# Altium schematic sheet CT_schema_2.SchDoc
size 276 x 169 mm
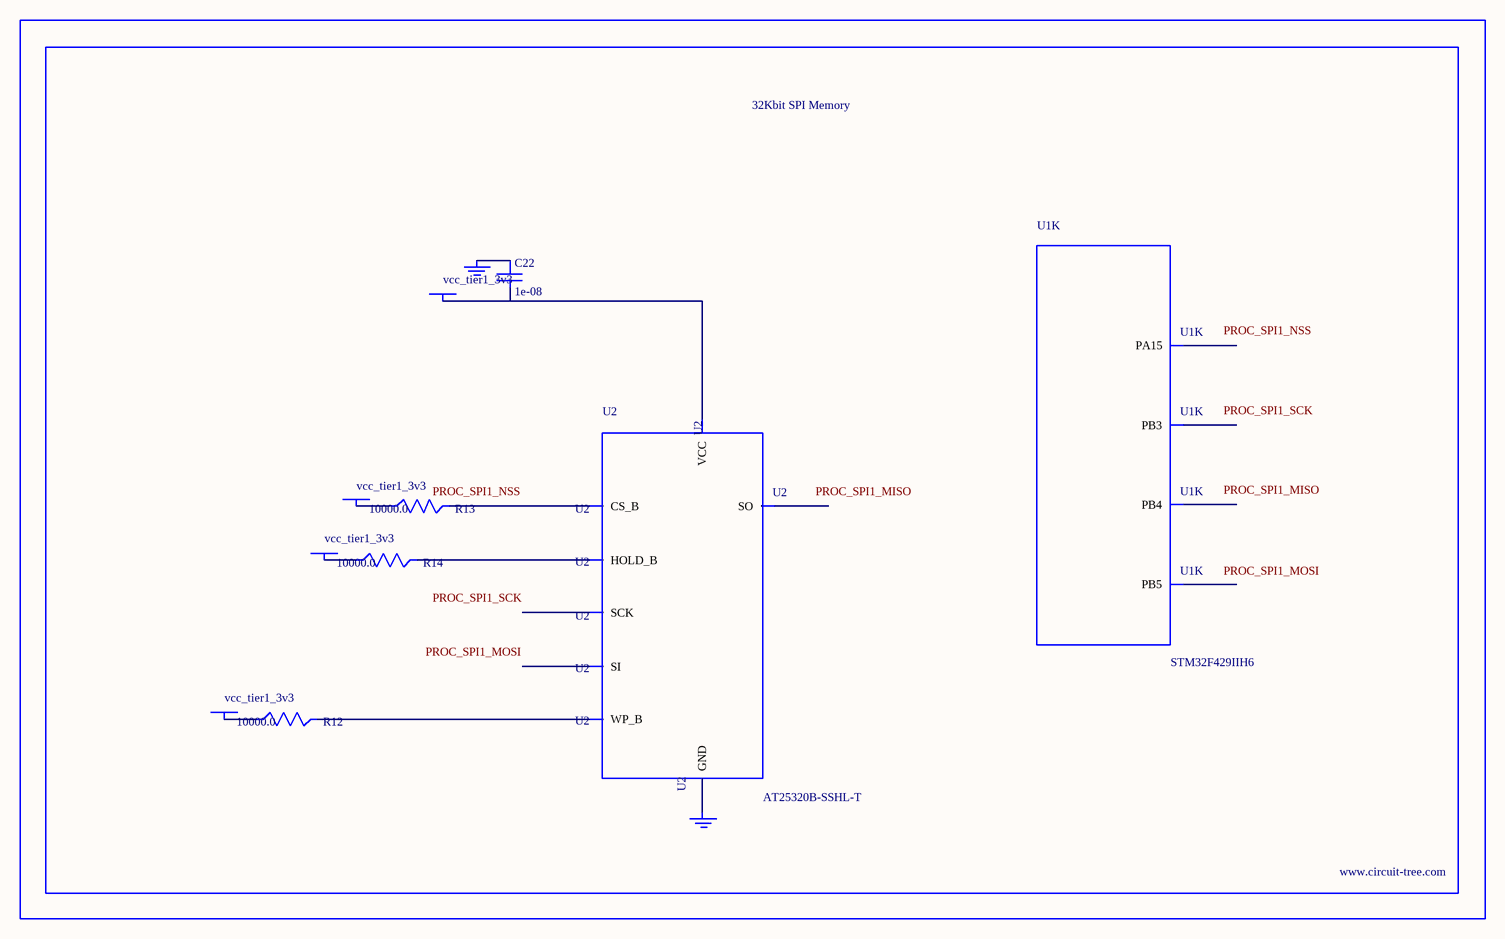
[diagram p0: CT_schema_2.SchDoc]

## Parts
BORDER1  (no value)
C22  1e-08  [C0402]
GND_INSTANCE_1_0  (no value)
GND_INSTANCE_1_1  (no value)
POWER_INSTANCE_1_0  vcc_tier1_3v3
POWER_INSTANCE_1_1  vcc_tier1_3v3
POWER_INSTANCE_1_2  vcc_tier1_3v3
POWER_INSTANCE_1_3  vcc_tier1_3v3
R12  10000.0  [R0603]
R13  10000.0  [R0603]
R14  10000.0  [R0603]
U1  STM32F429IIH6  [UFBGA176_25]  (part K of 16)
U2  AT25320B-SSHL-T  [SOIC-8]

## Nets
NetC22_1: C22.1 GND_INSTANCE_1_0.0(GND)
NetC22_2: C22.2 POWER_INSTANCE_1_3.0(PWR) U2.8(VCC)
NetGND_INSTANCE_1_1_0: GND_INSTANCE_1_1.0(GND) U2.4(GND)
NetPOWER_INSTANCE_1_0_0: POWER_INSTANCE_1_0.0(PWR) R13.1
NetPOWER_INSTANCE_1_1_0: POWER_INSTANCE_1_1.0(PWR) R12.1
NetPOWER_INSTANCE_1_2_0: POWER_INSTANCE_1_2.0(PWR) R14.1
NetR12_2: R12.2 U2.3(WP_B)
NetR13_2: R13.2 U2.1(CS_B)
NetR14_2: R14.2 U2.7(HOLD_B)

Not connected (* = marked no-connect by the designer): U1 A6(PB5) A9(PB4) A10(PB3) A13(PA15); U2 2(SO) 5(SI) 6(SCK)

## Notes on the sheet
- Labels drawn without touching a wire or pin: PROC_SPI1_MISO, PROC_SPI1_MOSI, PROC_SPI1_NSS, PROC_SPI1_SCK

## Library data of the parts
BORDER1 = BORDER_PAGE1
C22 = C0402C103K3RAC
GND_INSTANCE_1_0 GND_INSTANCE_1_1 = GND
POWER_INSTANCE_1_0-POWER_INSTANCE_1_3 = PWR
R12-R14 = RC0603JR-0710KL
